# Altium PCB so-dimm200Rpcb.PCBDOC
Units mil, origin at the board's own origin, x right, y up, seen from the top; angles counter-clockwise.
Board outline 6000 x 4000 mil, 2 copper layers (Top Layer, Bottom Layer); 3 components, 0 nets, 612 pads, 0 vias.
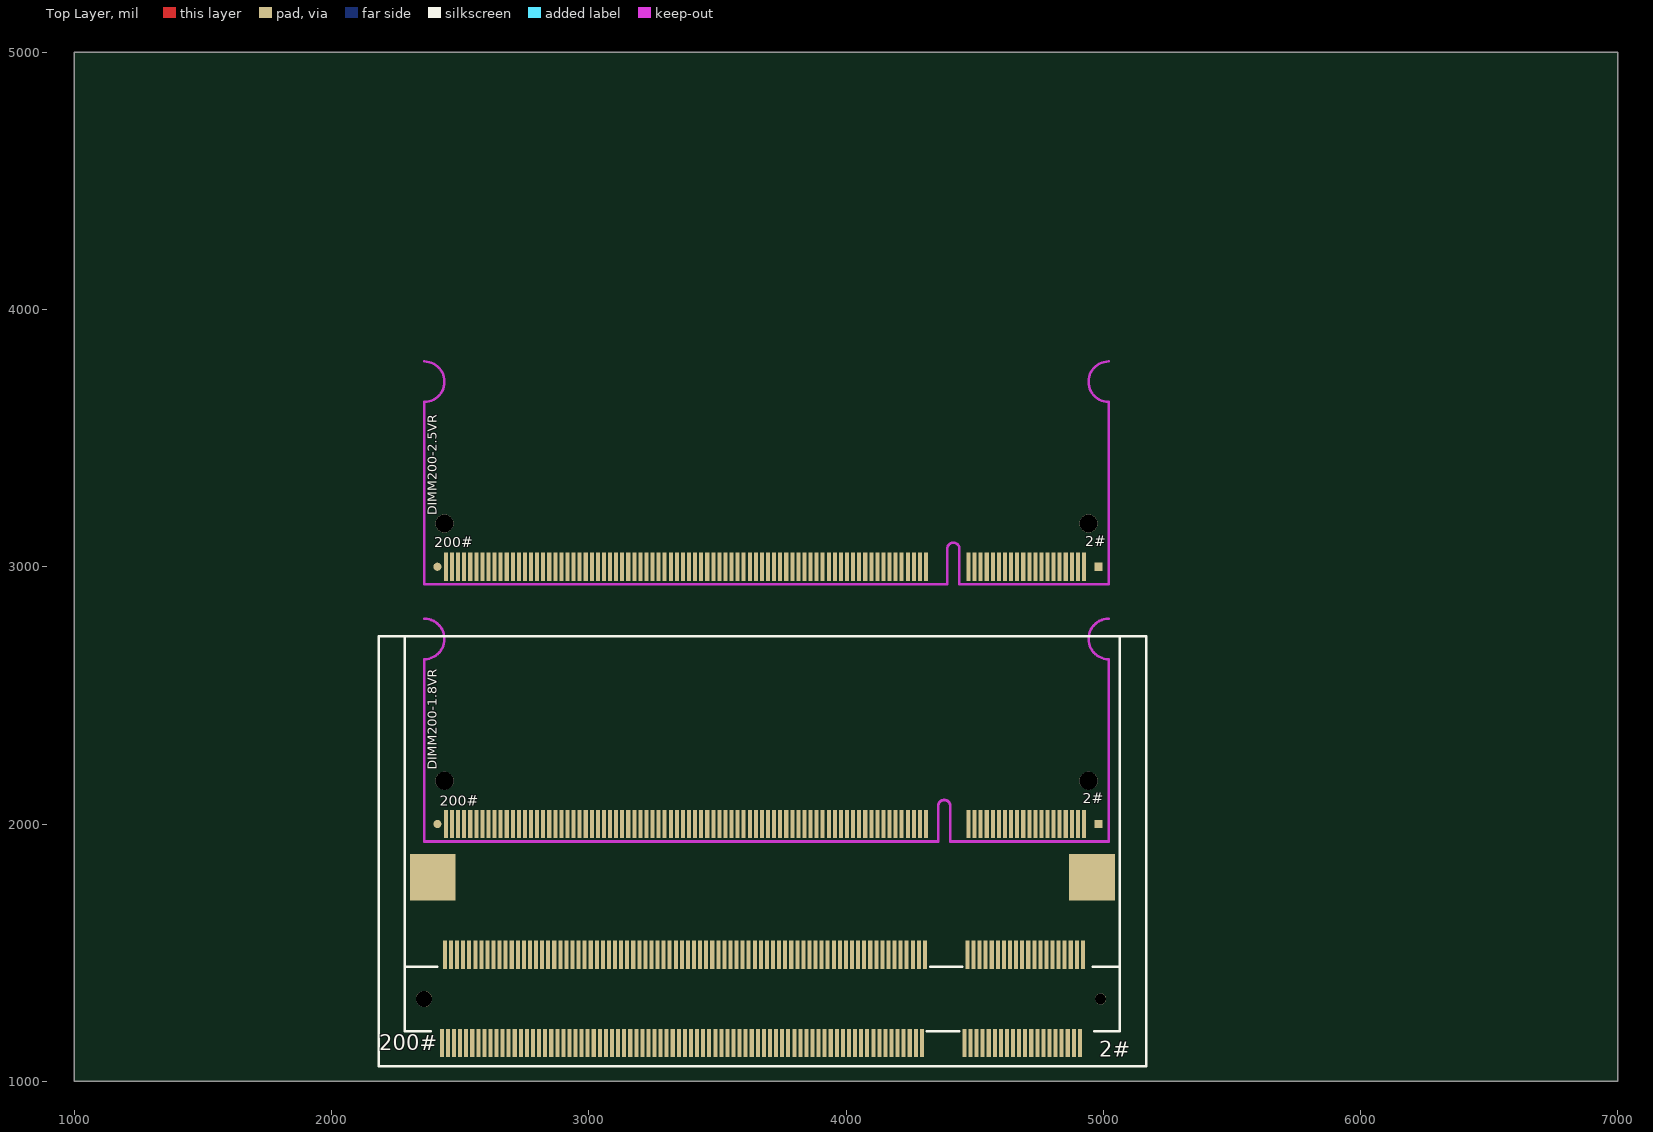
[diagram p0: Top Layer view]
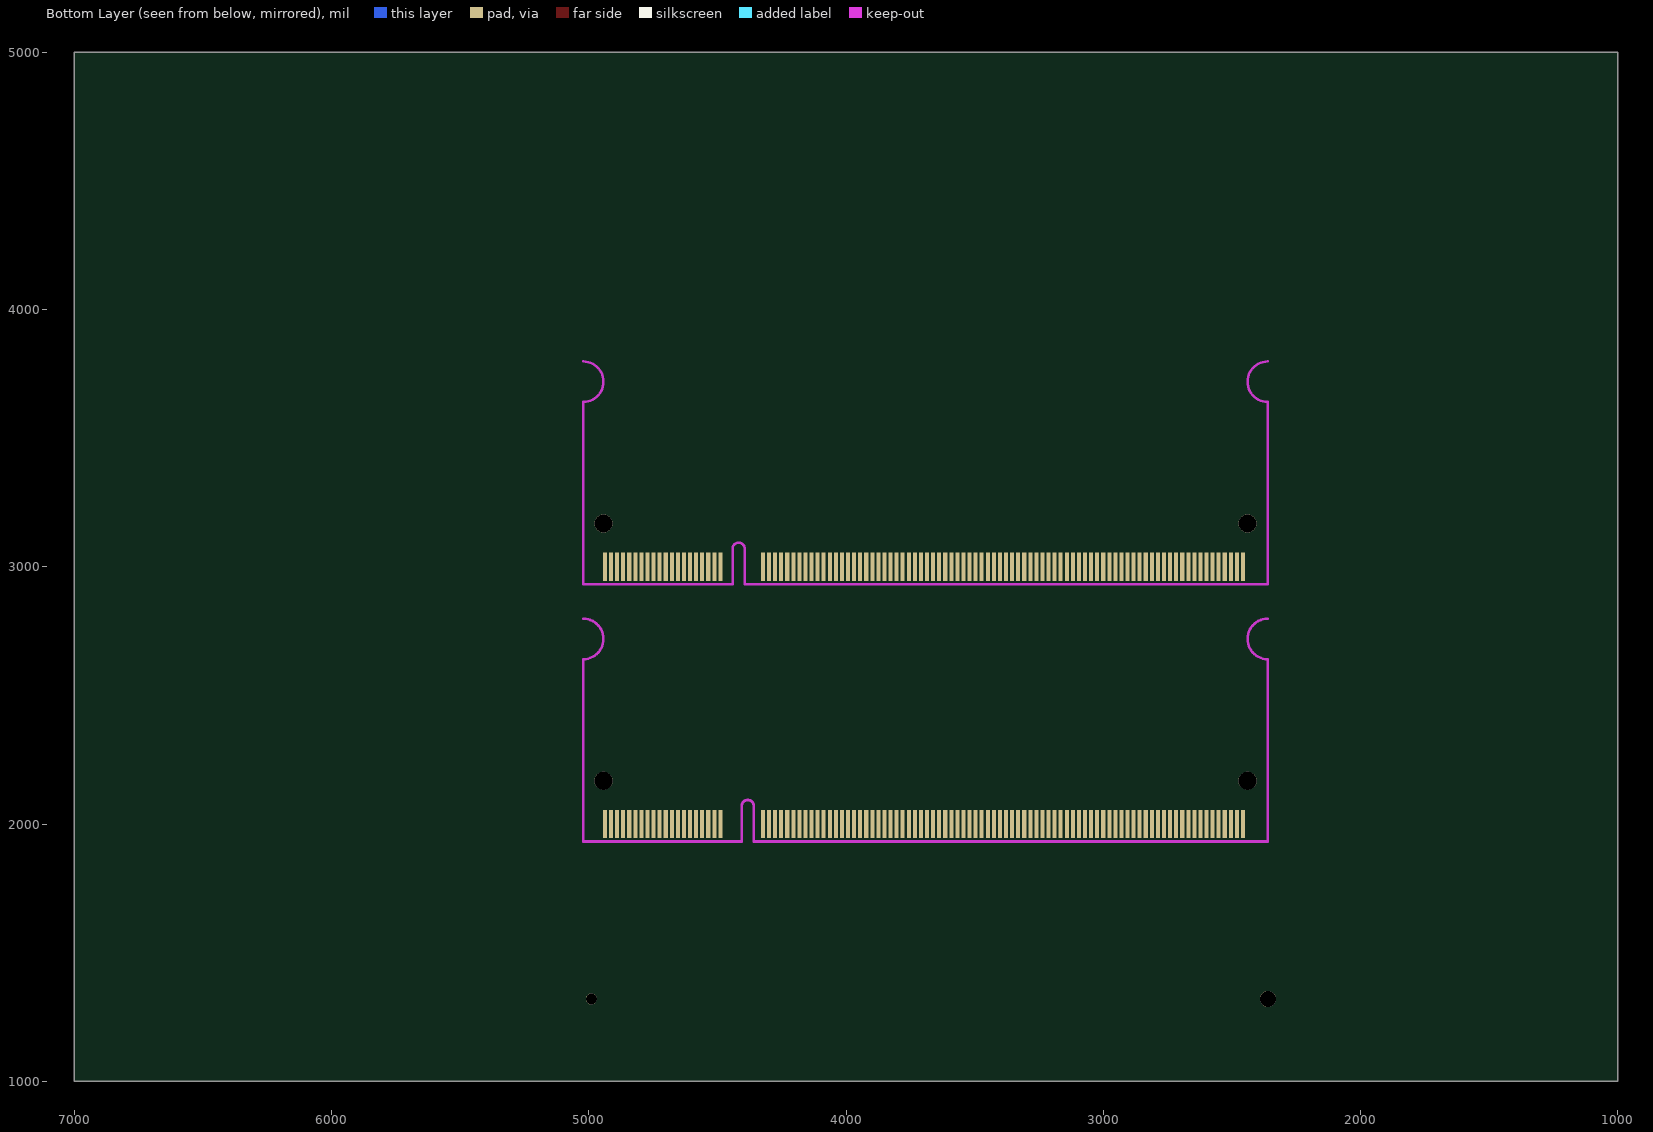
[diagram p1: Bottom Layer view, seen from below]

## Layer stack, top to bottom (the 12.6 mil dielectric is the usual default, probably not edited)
Top Layer: signal copper 1.4
Dielectric: dielectric 12.6, FR-4, Dk 4.8
Bottom Layer: signal copper 1.4

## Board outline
1000,1000 7000,1000 7000,5000 1000,5000

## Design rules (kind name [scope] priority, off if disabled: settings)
Clearance [All] p1: gap=10
ComponentClearance [All] p1: gap=10 collisioncheckmode=0
PolygonConnect [All] p1: connectstyle=Relief reliefconductorwidth=10 reliefentries=4 polygonreliefangle="90 Angle"
RoutingLayers [All] p1: top layer=Horizontal bottom layer=Vertical
RoutingVias [All] p1: holewidth=28 width=50 viastyle="Through Hole" minholewidth=28 minwidth=50 maxholewidth=28 maxwidth=50
SolderMaskExpansion [All] p1: expansion=4
TestPointUsage [All] p1: valid=0 allowmultiple=FALSE
Testpoint [All] p1: side=15 testpointundercomponent=TRUE minsize=40 maxsize=100 preferedsize=60 minholesize=0 maxholesize=40 preferedholesize=32 testpointgrid=1 style=1023 order=1234567890
Width [All] p1: maxlimit=10 minlimit=10 preferedwidth=10
16 further rules are at their usual default settings.

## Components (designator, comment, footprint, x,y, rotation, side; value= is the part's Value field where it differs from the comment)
? "Comment" "SO-DIMM200RX " 2360,1320 r0 top
? "Comment" SO-DIMM200r 3000,2000 r0 top
? "Comment" SO-DIMM200V25r 3000,3000 r0 top

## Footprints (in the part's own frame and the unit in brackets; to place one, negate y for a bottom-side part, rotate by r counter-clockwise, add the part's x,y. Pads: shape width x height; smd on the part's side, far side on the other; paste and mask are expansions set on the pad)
SO-DIMM200r [mm]
  round 0.8 smd: 0(-14.94,0)
  round 1.8 hole 1.8: 0(-14.25,4.273) 0(49.35,4.273)
  rect 0.8x0.8 smd: 0(50.34,0)
  rect 0.4x2.8 smd far side: A1(49.2,0) A2(48.6,0) A3(48,0) A4(47.4,0) A5(46.8,0) A6(46.2,0) A7(45.6,0) A8(45,0) A9(44.4,0) A10(43.8,0) A11(43.2,0) A12(42.6,0) A13(42,0) A14(41.4,0) A15(40.8,0) A16(40.2,0) A17(39.6,0) A18(39,0) A19(38.4,0) A20(37.8,0) A21(33.6,0) A22(33,0) A23(32.4,0) A24(31.8,0) A25(31.2,0) A26(30.6,0) A27(30,0) A28(29.4,0) A29(28.8,0) A30(28.2,0) A31(27.6,0) A32(27,0) A33(26.4,0) A34(25.8,0) A35(25.2,0) A36(24.6,0) A37(24,0) A38(23.4,0) A39(22.8,0) A40(22.2,0) A41(21.6,0) A42(21,0) A43(20.4,0) A44(19.8,0) A45(19.2,0) A46(18.6,0) A47(18,0) A48(17.4,0) A49(16.8,0) A50(16.2,0) A51(15.6,0) A52(15,0) A53(14.4,0) A54(13.8,0) A55(13.2,0) A56(12.6,0) A57(12,0) A58(11.4,0) A59(10.8,0) A60(10.2,0) A61(9.6,0) A62(9,0) A63(8.4,0) A64(7.8,0) A65(7.2,0) A66(6.6,0) A67(6,0) A68(5.4,0) A69(4.8,0) A70(4.2,0) A71(3.6,0) A72(3,0) A73(2.4,0) A74(1.8,0) A75(1.2,0) A76(0.6,0) A77(0,0) A78(-0.6,0) A79(-1.2,0) A80(-1.8,0) A81(-2.4,0) A82(-3,0) A83(-3.6,0) A84(-4.2,0) A85(-4.8,0) A86(-5.4,0) A87(-6,0) A88(-6.6,0) A89(-7.2,0) A90(-7.8,0) A91(-8.4,0) A92(-9,0) A93(-9.6,0) A94(-10.2,0) A95(-10.8,0) A96(-11.4,0) A97(-12,0) A98(-12.6,0) A99(-13.2,0) A100(-13.8,0)
  rect 0.4x2.8 smd: B1(48.9,0) B2(48.3,0) B3(47.7,0) B4(47.1,0) B5(46.5,0) B6(45.9,0) B7(45.3,0) B8(44.7,0) B9(44.1,0) B10(43.5,0) B11(42.9,0) B12(42.3,0) B13(41.7,0) B14(41.1,0) B15(40.5,0) B16(39.9,0) B17(39.3,0) B18(38.7,0) B19(38.1,0) B20(37.5,0) B21(33.3,0) B22(32.7,0) B23(32.1,0) B24(31.5,0) B25(30.9,0) B26(30.3,0) B27(29.7,0) B28(29.1,0) B29(28.5,0) B30(27.9,0) B31(27.3,0) B32(26.7,0) B33(26.1,0) B34(25.5,0) B35(24.9,0) B36(24.3,0) B37(23.7,0) B38(23.1,0) B39(22.5,0) B40(21.9,0) B41(21.3,0) B42(20.7,0) B43(20.1,0) B44(19.5,0) B45(18.9,0) B46(18.3,0) B47(17.7,0) B48(17.1,0) B49(16.5,0) B50(15.9,0) B51(15.3,0) B52(14.7,0) B53(14.1,0) B54(13.5,0) B55(12.9,0) B56(12.3,0) B57(11.7,0) B58(11.1,0) B59(10.5,0) B60(9.9,0) B61(9.3,0) B62(8.7,0) B63(8.1,0) B64(7.5,0) B65(6.9,0) B66(6.3,0) B67(5.7,0) B68(5.1,0) B69(4.5,0) B70(3.9,0) B71(3.3,0) B72(2.7,0) B73(2.1,0) B74(1.5,0) B75(0.9,0) B76(0.3,0) B77(-0.3,0) B78(-0.9,0) B79(-1.5,0) B80(-2.1,0) B81(-2.7,0) B82(-3.3,0) B83(-3.9,0) B84(-4.5,0) B85(-5.1,0) B86(-5.7,0) B87(-6.3,0) B88(-6.9,0) B89(-7.5,0) B90(-8.1,0) B91(-8.7,0) B92(-9.3,0) B93(-9.9,0) B94(-10.5,0) B95(-11.1,0) B96(-11.7,0) B97(-12.3,0) B98(-12.9,0) B99(-13.5,0) B100(-14.1,0)
  Keep-Out Layer lines w0.254: -16.25,20.273 cw(c-16.25,18.273) -16.25,16.273 -16.25,-1.727 34.5,-1.727 34.5,1.773 cw(c35.1,1.773) 35.7,1.773 35.7,-1.727 51.35,-1.727 51.35,16.273 cw(c51.35,18.273) 51.35,20.273
"SO-DIMM200RX " [mm]
  round 1.6 hole 1.6: 0(0,0)
  rect 4.5x4.6 smd: 0(0.85,12) 0(65.95,12)
  round 1.1 hole 1.1: 0(66.8,0)
  rect 0.4x2.8 smd: A1(65.05,4.35) A2(64.45,4.35) A3(63.85,4.35) A4(63.25,4.35) A5(62.65,4.35) A6(62.05,4.35) A7(61.45,4.35) A8(60.85,4.35) A9(60.25,4.35) A10(59.65,4.35) A11(59.05,4.35) A12(58.45,4.35) A13(57.85,4.35) A14(57.25,4.35) A15(56.65,4.35) A16(56.05,4.35) A17(55.45,4.35) A18(54.85,4.35) A19(54.25,4.35) A20(53.65,4.35) A21(49.45,4.35) A22(48.85,4.35) A23(48.25,4.35) A24(47.65,4.35) A25(47.05,4.35) A26(46.45,4.35) A27(45.85,4.35) A28(45.25,4.35) A29(44.65,4.35) A30(44.05,4.35) A31(43.45,4.35) A32(42.85,4.35) A33(42.25,4.35) A34(41.65,4.35) A35(41.05,4.35) A36(40.45,4.35) A37(39.85,4.35) A38(39.25,4.35) A39(38.65,4.35) A40(38.05,4.35) A41(37.45,4.35) A42(36.85,4.35) A43(36.25,4.35) A44(35.65,4.35) A45(35.05,4.35) A46(34.45,4.35) A47(33.85,4.35) A48(33.25,4.35) A49(32.65,4.35) A50(32.05,4.35) A51(31.45,4.35) A52(30.85,4.35) A53(30.25,4.35) A54(29.65,4.35) A55(29.05,4.35) A56(28.45,4.35) A57(27.85,4.35) A58(27.25,4.35) A59(26.65,4.35) A60(26.05,4.35) A61(25.45,4.35) A62(24.85,4.35) A63(24.25,4.35) A64(23.65,4.35) A65(23.05,4.35) A66(22.45,4.35) A67(21.85,4.35) A68(21.25,4.35) A69(20.65,4.35) A70(20.05,4.35) A71(19.45,4.35) A72(18.85,4.35) A73(18.25,4.35) A74(17.65,4.35) A75(17.05,4.35) A76(16.45,4.35) A77(15.85,4.35) A78(15.25,4.35) A79(14.65,4.35) A80(14.05,4.35) A81(13.45,4.35) A82(12.85,4.35) A83(12.25,4.35) A84(11.65,4.35) A85(11.05,4.35) A86(10.45,4.35) A87(9.85,4.35) A88(9.25,4.35) A89(8.65,4.35) A90(8.05,4.35) A91(7.45,4.35) A92(6.85,4.35) A93(6.25,4.35) A94(5.65,4.35) A95(5.05,4.35) A96(4.45,4.35) A97(3.85,4.35) A98(3.25,4.35) A99(2.65,4.35) A100(2.05,4.35) B1(64.75,-4.35) B2(64.15,-4.35) B3(63.55,-4.35) B4(62.95,-4.35) B5(62.35,-4.35) B6(61.75,-4.35) B7(61.15,-4.35) B8(60.55,-4.35) B9(59.95,-4.35) B10(59.35,-4.35) B11(58.75,-4.35) B12(58.15,-4.35) B13(57.55,-4.35) B14(56.95,-4.35) B15(56.35,-4.35) B16(55.75,-4.35) B17(55.15,-4.35) B18(54.55,-4.35) B19(53.95,-4.35) B20(53.35,-4.35) B21(49.15,-4.35) B22(48.55,-4.35) B23(47.95,-4.35) B24(47.35,-4.35) B25(46.75,-4.35) B26(46.15,-4.35) B27(45.55,-4.35) B28(44.95,-4.35) B29(44.35,-4.35) B30(43.75,-4.35) B31(43.15,-4.35) B32(42.55,-4.35) B33(41.95,-4.35) B34(41.35,-4.35) B35(40.75,-4.35) B36(40.15,-4.35) B37(39.55,-4.35) B38(38.95,-4.35) B39(38.35,-4.35) B40(37.75,-4.35) B41(37.15,-4.35) B42(36.55,-4.35) B43(35.95,-4.35) B44(35.35,-4.35) B45(34.75,-4.35) B46(34.15,-4.35) B47(33.55,-4.35) B48(32.95,-4.35) B49(32.35,-4.35) B50(31.75,-4.35) B51(31.15,-4.35) B52(30.55,-4.35) B53(29.95,-4.35) B54(29.35,-4.35) B55(28.75,-4.35) B56(28.15,-4.35) B57(27.55,-4.35) B58(26.95,-4.35) B59(26.35,-4.35) B60(25.75,-4.35) B61(25.15,-4.35) B62(24.55,-4.35) B63(23.95,-4.35) B64(23.35,-4.35) B65(22.75,-4.35) B66(22.15,-4.35) B67(21.55,-4.35) B68(20.95,-4.35) B69(20.35,-4.35) B70(19.75,-4.35) B71(19.15,-4.35) B72(18.55,-4.35) B73(17.95,-4.35) B74(17.35,-4.35) B75(16.75,-4.35) B76(16.15,-4.35) B77(15.55,-4.35) B78(14.95,-4.35) B79(14.35,-4.35) B80(13.75,-4.35) B81(13.15,-4.35) B82(12.55,-4.35) B83(11.95,-4.35) B84(11.35,-4.35) B85(10.75,-4.35) B86(10.15,-4.35) B87(9.55,-4.35) B88(8.95,-4.35) B89(8.35,-4.35) B90(7.75,-4.35) B91(7.15,-4.35) B92(6.55,-4.35) B93(5.95,-4.35) B94(5.35,-4.35) B95(4.75,-4.35) B96(4.15,-4.35) B97(3.55,-4.35) B98(2.95,-4.35) B99(2.35,-4.35) B100(1.75,-4.35)
  silkscreen extent -4.5,-6.64 71.3,35.8
SO-DIMM200V25r [mm]
  round 0.8 smd: 0(-14.94,0)
  round 1.8 hole 1.8: 0(-14.25,4.273) 0(49.35,4.273)
  rect 0.8x0.8 smd: 0(50.34,0)
  rect 0.4x2.8 smd far side: A1(49.2,0) A2(48.6,0) A3(48,0) A4(47.4,0) A5(46.8,0) A6(46.2,0) A7(45.6,0) A8(45,0) A9(44.4,0) A10(43.8,0) A11(43.2,0) A12(42.6,0) A13(42,0) A14(41.4,0) A15(40.8,0) A16(40.2,0) A17(39.6,0) A18(39,0) A19(38.4,0) A20(37.8,0) A21(33.6,0) A22(33,0) A23(32.4,0) A24(31.8,0) A25(31.2,0) A26(30.6,0) A27(30,0) A28(29.4,0) A29(28.8,0) A30(28.2,0) A31(27.6,0) A32(27,0) A33(26.4,0) A34(25.8,0) A35(25.2,0) A36(24.6,0) A37(24,0) A38(23.4,0) A39(22.8,0) A40(22.2,0) A41(21.6,0) A42(21,0) A43(20.4,0) A44(19.8,0) A45(19.2,0) A46(18.6,0) A47(18,0) A48(17.4,0) A49(16.8,0) A50(16.2,0) A51(15.6,0) A52(15,0) A53(14.4,0) A54(13.8,0) A55(13.2,0) A56(12.6,0) A57(12,0) A58(11.4,0) A59(10.8,0) A60(10.2,0) A61(9.6,0) A62(9,0) A63(8.4,0) A64(7.8,0) A65(7.2,0) A66(6.6,0) A67(6,0) A68(5.4,0) A69(4.8,0) A70(4.2,0) A71(3.6,0) A72(3,0) A73(2.4,0) A74(1.8,0) A75(1.2,0) A76(0.6,0) A77(0,0) A78(-0.6,0) A79(-1.2,0) A80(-1.8,0) A81(-2.4,0) A82(-3,0) A83(-3.6,0) A84(-4.2,0) A85(-4.8,0) A86(-5.4,0) A87(-6,0) A88(-6.6,0) A89(-7.2,0) A90(-7.8,0) A91(-8.4,0) A92(-9,0) A93(-9.6,0) A94(-10.2,0) A95(-10.8,0) A96(-11.4,0) A97(-12,0) A98(-12.6,0) A99(-13.2,0) A100(-13.8,0)
  rect 0.4x2.8 smd: B1(48.9,0) B2(48.3,0) B3(47.7,0) B4(47.1,0) B5(46.5,0) B6(45.9,0) B7(45.3,0) B8(44.7,0) B9(44.1,0) B10(43.5,0) B11(42.9,0) B12(42.3,0) B13(41.7,0) B14(41.1,0) B15(40.5,0) B16(39.9,0) B17(39.3,0) B18(38.7,0) B19(38.1,0) B20(37.5,0) B21(33.3,0) B22(32.7,0) B23(32.1,0) B24(31.5,0) B25(30.9,0) B26(30.3,0) B27(29.7,0) B28(29.1,0) B29(28.5,0) B30(27.9,0) B31(27.3,0) B32(26.7,0) B33(26.1,0) B34(25.5,0) B35(24.9,0) B36(24.3,0) B37(23.7,0) B38(23.1,0) B39(22.5,0) B40(21.9,0) B41(21.3,0) B42(20.7,0) B43(20.1,0) B44(19.5,0) B45(18.9,0) B46(18.3,0) B47(17.7,0) B48(17.1,0) B49(16.5,0) B50(15.9,0) B51(15.3,0) B52(14.7,0) B53(14.1,0) B54(13.5,0) B55(12.9,0) B56(12.3,0) B57(11.7,0) B58(11.1,0) B59(10.5,0) B60(9.9,0) B61(9.3,0) B62(8.7,0) B63(8.1,0) B64(7.5,0) B65(6.9,0) B66(6.3,0) B67(5.7,0) B68(5.1,0) B69(4.5,0) B70(3.9,0) B71(3.3,0) B72(2.7,0) B73(2.1,0) B74(1.5,0) B75(0.9,0) B76(0.3,0) B77(-0.3,0) B78(-0.9,0) B79(-1.5,0) B80(-2.1,0) B81(-2.7,0) B82(-3.3,0) B83(-3.9,0) B84(-4.5,0) B85(-5.1,0) B86(-5.7,0) B87(-6.3,0) B88(-6.9,0) B89(-7.5,0) B90(-8.1,0) B91(-8.7,0) B92(-9.3,0) B93(-9.9,0) B94(-10.5,0) B95(-11.1,0) B96(-11.7,0) B97(-12.3,0) B98(-12.9,0) B99(-13.5,0) B100(-14.1,0)
  Keep-Out Layer lines w0.254: -16.25,20.273 cw(c-16.25,18.273) -16.25,16.273 -16.25,-1.727 35.4,-1.727 35.4,1.773 cw(c36,1.773) 36.6,1.773 36.6,-1.727 51.35,-1.727 51.35,16.273 cw(c51.35,18.273) 51.35,20.273

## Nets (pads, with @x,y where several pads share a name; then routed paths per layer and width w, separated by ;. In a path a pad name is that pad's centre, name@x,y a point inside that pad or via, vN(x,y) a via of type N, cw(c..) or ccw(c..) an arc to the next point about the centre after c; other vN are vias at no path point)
pads on no net: ?.0 ?.A1 ?.A2 ?.A3 ?.A4 ?.A5 ?.A6 ?.A7 ?.A8 ?.A9 ?.A10 ?.A11 ?.A12 ?.A13 ?.A14 ?.A15 ?.A16 ?.A17 ?.A18 ?.A19 ?.A20 ?.A21 ?.A22 ?.A23 ?.A24 ?.A25 ?.A26 ?.A27 ?.A28 ?.A29 ?.A30 ?.A31 ?.A32 ?.A33 ?.A34 ?.A35 ?.A36 ?.A37 ?.A38 ?.A39 ?.A40 ?.A41 ?.A42 ?.A43 ?.A44 ?.A45 ?.A46 ?.A47 ?.A48 ?.A49 ?.A50 ?.A51 ?.A52 ?.A53 ?.A54 ?.A55 ?.A56 ?.A57 ?.A58 ?.A59 ?.A60 ?.A61 ?.A62 ?.A63 ?.A64 ?.A65 ?.A66 ?.A67 ?.A68 ?.A69 ?.A70 ?.A71 ?.A72 ?.A73 ?.A74 ?.A75 ?.A76 ?.A77 ?.A78 ?.A79 ?.A80 ?.A81 ?.A82 ?.A83 ?.A84 ?.A85 ?.A86 ?.A87 ?.A88 ?.A89 ?.A90 ?.A91 ?.A92 ?.A93 ?.A94 ?.A95 ?.A96 ?.A97 ?.A98 ?.A99 ?.A100 ?.B1 ?.B2 ?.B3 ?.B4 ?.B5 ?.B6 ?.B7 ?.B8 ?.B9 ?.B10 ?.B11 ?.B12 ?.B13 ?.B14 ?.B15 ?.B16 ?.B17 ?.B18 ?.B19 ?.B20 ?.B21 ?.B22 ?.B23 ?.B24 ?.B25 ?.B26 ?.B27 ?.B28 ?.B29 ?.B30 ?.B31 ?.B32 ?.B33 ?.B34 ?.B35 ?.B36 ?.B37 ?.B38 ?.B39 ?.B40 ?.B41 ?.B42 ?.B43 ?.B44 ?.B45 ?.B46 ?.B47 ?.B48 ?.B49 ?.B50 ?.B51 ?.B52 ?.B53 ?.B54 ?.B55 ?.B56 ?.B57 ?.B58 ?.B59 ?.B60 ?.B61 ?.B62 ?.B63 ?.B64 ?.B65 ?.B66 ?.B67 ?.B68 ?.B69 ?.B70 ?.B71 ?.B72 ?.B73 ?.B74 ?.B75 ?.B76 ?.B77 ?.B78 ?.B79 ?.B80 ?.B81 ?.B82 ?.B83 ?.B84 ?.B85 ?.B86 ?.B87 ?.B88 ?.B89 ?.B90 ?.B91 ?.B92 ?.B93 ?.B94 ?.B95 ?.B96 ?.B97 ?.B98 ?.B99 ?.B100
